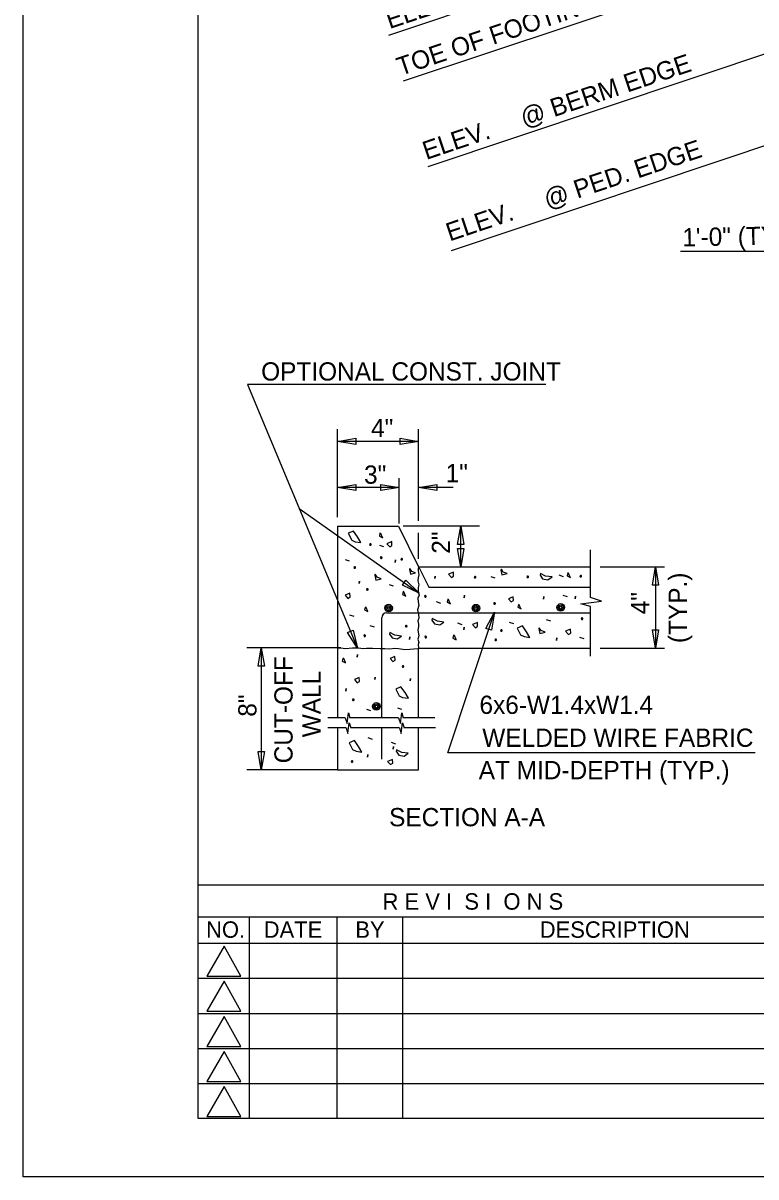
# Model space of a CAD drawing. Extents: x 0 to 272, y 0 to 188.
# Drawn here: x 0 to 50.2, y 0 to 79 of the extents above; entities that cross this region are included whole.
import ezdxf

# ---------------------------------------------------------------- set-up
doc = ezdxf.new("R2010")
doc.units = 0
for name, color, linetype in [('BORDER_ANNO_Cutsheet', 7, 'Continuous'), ('BRDG_ANNO_Anno-Sheet', 7, 'Continuous'), ('BRDG_ANNO_General-Notes', 7, 'Continuous'), ('BRDG_BASE_Active-Point', 7, 'Continuous'), ('BRDG_BASE_Hidden-Line', 7, 'Continuous'), ('BRDG_BASE_Obj-Line', 7, 'Continuous'), ('BRDG_BASE_Pattern', 7, 'Continuous'), ('BRDG_BASE_Rebar', 7, 'Continuous')]:
    doc.layers.add(name, color=color, linetype=linetype)

msp = doc.modelspace()

# ---------------------------------------------------------------- linework, layer by layer
at = {"layer": 'BORDER_ANNO_Cutsheet'}
msp.add_lwpolyline([(0, 176), (272, 176), (272, 0), (0, 0)], close=True, dxfattribs=at)
at = {"layer": 'BRDG_ANNO_Anno-Sheet'}
for p, q in [((12, 20), (154, 20)), ((12, 17.8), (56, 17.8)), ((15.5, 4), (15.5, 17.8)), ((21.5, 4), (21.5, 17.8)), ((26, 4), (26, 17.755)), ((11.98, 16), (56, 16)), ((11.98, 13.6), (56, 13.6)), ((11.98, 11.2), (56, 11.2)), ((11.98, 8.8), (56, 8.8)), ((11.98, 6.4), (56, 6.4))]:
    msp.add_line(p, q, dxfattribs=at)
msp.add_lwpolyline([(12, 172), (268, 172), (268, 4), (12, 4)], close=True, dxfattribs=at)
for points in [[(13.78, 15.795), (12.595, 13.74), (14.915, 13.74), (13.78, 15.795)], [(13.78, 13.395), (12.595, 11.34), (14.915, 11.34), (13.78, 13.395)], [(13.78, 10.995), (12.595, 8.94), (14.915, 8.94), (13.78, 10.995)], [(13.78, 8.595), (12.595, 6.54), (14.915, 6.54), (13.78, 8.595)], [(13.78, 6.195), (12.595, 4.14), (14.915, 4.14), (13.78, 6.195)]]:
    msp.add_lwpolyline(points, dxfattribs=at)
at = {"layer": 'BRDG_ANNO_General-Notes'}
for p, q in [((25.039, 78.187), (58.643, 89.43)), ((26.054, 75.048), (57.783, 85.664)), ((27.736, 69.191), (51.823, 77.251)), ((29.335, 63.443), (52.01, 71.029)), ((45.029, 63.39), (54.706, 63.39)), ((15.359, 54.256), (22.894, 36.209)), ((35.8, 54.256), (15.359, 54.256)), ((21.53, 45.18), (21.53, 51.205)), ((21.53, 50.37), (22.78, 50.578)), ((22.78, 50.578), (22.78, 50.162)), ((25.827, 50.162), (25.827, 50.578)), ((25.827, 50.578), (27.077, 50.37)), ((27.089, 44.917), (27.089, 51.205)), ((27.077, 50.37), (21.53, 50.37)), ((22.78, 50.162), (21.53, 50.37)), ((27.077, 50.37), (25.827, 50.162)), ((21.53, 47.213), (22.78, 47.422)), ((22.78, 47.422), (22.78, 47.005)), ((24.502, 47.005), (24.502, 47.422)), ((24.502, 47.422), (25.752, 47.213)), ((25.752, 44.74), (25.752, 47.838)), ((27.089, 47.213), (28.339, 47.422)), ((28.339, 47.422), (28.339, 47.005)), ((25.752, 47.213), (21.53, 47.213)), ((22.78, 47.005), (21.53, 47.213)), ((25.752, 47.213), (24.502, 47.005)), ((29.449, 47.213), (27.089, 47.213)), ((28.339, 47.005), (27.089, 47.213)), ((18.903, 45.769), (27.119, 39.965)), ((31.246, 44.555), (26.022, 44.555)), ((29.761, 43.305), (29.969, 44.555)), ((29.969, 41.784), (29.969, 44.555)), ((29.969, 44.555), (30.178, 43.305)), ((27.089, 42.32), (27.089, 44.102)), ((30.178, 43.305), (29.761, 43.305)), ((29.761, 43.034), (30.178, 43.034)), ((29.969, 41.784), (29.761, 43.034)), ((30.178, 43.034), (29.969, 41.784)), ((39.527, 41.776), (43.937, 41.776)), ((43.104, 40.526), (43.312, 41.776)), ((43.312, 41.776), (43.312, 36.217)), ((43.312, 41.776), (43.521, 40.526)), ((25.978, 40.516), (26.219, 40.856)), ((27.119, 39.965), (25.978, 40.516)), ((26.219, 40.856), (27.119, 39.965)), ((43.521, 40.526), (43.104, 40.526)), ((29.084, 29.032), (32.284, 38.684)), ((31.693, 37.563), (32.284, 38.684)), ((32.284, 38.684), (32.089, 37.432)), ((22.22, 37.282), (22.604, 37.443)), ((22.894, 36.209), (22.22, 37.282)), ((22.604, 37.443), (22.894, 36.209)), ((32.089, 37.432), (31.693, 37.563)), ((43.104, 37.467), (43.521, 37.467)), ((43.312, 36.217), (43.104, 37.467)), ((43.521, 37.467), (43.312, 36.217)), ((21.767, 36.221), (15.334, 36.221)), ((16.106, 34.971), (16.314, 36.221)), ((16.314, 36.221), (16.314, 27.878)), ((16.314, 36.221), (16.523, 34.971)), ((39.527, 36.217), (43.937, 36.217)), ((16.523, 34.971), (16.106, 34.971)), ((16.106, 29.128), (16.523, 29.128)), ((16.314, 27.878), (16.106, 29.128)), ((16.523, 29.128), (16.314, 27.878)), ((50.13, 29.032), (29.084, 29.032)), ((21.53, 27.878), (15.334, 27.878))]:
    msp.add_line(p, q, dxfattribs=at)
at = {"layer": 'BRDG_BASE_Active-Point'}
msp.add_line((0, 0), (0, 0), dxfattribs=at)
at = {"layer": 'BRDG_BASE_Hidden-Line'}
for p, q in [((27.123, 41.708), (27.782, 40.391)), ((27.782, 40.386), (38.869, 40.386))]:
    msp.add_line(p, q, dxfattribs=at)
at = {"layer": 'BRDG_BASE_Obj-Line'}
for p, q in [((21.53, 44.555), (25.699, 44.555)), ((21.53, 44.555), (21.53, 31.444)), ((25.699, 44.555), (27.089, 41.776)), ((38.869, 39.673), (38.869, 42.936)), ((27.089, 41.776), (27.093, 41.776)), ((27.089, 41.776), (38.869, 41.776)), ((39.619, 39.43), (38.869, 39.673)), ((38.197, 39.241), (39.619, 39.43)), ((38.869, 39.05), (38.197, 39.241)), ((38.869, 35.657), (38.869, 39.05)), ((27.089, 31.444), (27.089, 36.217)), ((27.089, 36.217), (38.869, 36.217)), ((22.194, 31.048), (22.29, 31.778)), ((22.29, 31.778), (22.388, 31.435)), ((25.844, 31.048), (25.941, 31.778)), ((25.941, 31.778), (26.038, 31.435)), ((22.069, 31.435), (20.875, 31.435)), ((22.069, 31.435), (22.194, 31.048)), ((22.242, 30.369), (22.338, 31.099)), ((22.338, 31.099), (22.437, 30.755)), ((25.72, 31.435), (22.388, 31.435)), ((25.72, 31.435), (25.844, 31.048)), ((25.893, 30.369), (25.99, 31.099)), ((25.99, 31.099), (26.087, 30.755)), ((28.198, 31.435), (26.038, 31.435)), ((22.117, 30.755), (20.874, 30.756)), ((21.53, 30.741), (21.53, 27.878)), ((22.117, 30.755), (22.242, 30.369)), ((25.769, 30.755), (22.437, 30.755)), ((25.769, 30.755), (25.893, 30.369)), ((28.246, 30.755), (26.087, 30.755)), ((27.089, 27.878), (27.089, 30.741)), ((21.53, 27.878), (27.089, 27.878))]:
    msp.add_line(p, q, dxfattribs=at)
for points in [[(27.094, 41.756), (27.063, 41.696), (27.054, 41.501), (27.104, 41.237), (27.063, 41.024), (27.033, 40.81), (27.104, 40.546), (27.054, 40.353), (27.054, 40.099), (27.124, 39.835), (27.023, 39.632), (27.054, 39.378), (27.094, 39.123), (27.013, 38.829), (27.074, 38.503), (27.104, 38.259), (27.023, 38.077), (27.084, 37.853), (27.084, 37.7), (27.044, 37.436), (27.104, 37.061), (27.023, 36.827), (27.094, 36.602), (27.063, 36.46), (27.074, 36.216)], [(21.538, 36.217), (21.767, 36.221), (22.072, 36.174), (22.553, 36.221), (22.976, 36.221), (23.293, 36.185), (23.516, 36.209), (23.927, 36.209), (24.455, 36.174), (24.783, 36.174), (25.112, 36.162), (25.453, 36.197), (25.711, 36.174), (26.145, 36.115), (26.497, 36.138), (26.755, 36.162), (27.084, 36.185)]]:
    msp.add_lwpolyline(points, dxfattribs=at)
at = {"layer": 'BRDG_BASE_Pattern'}
for p, q in [((24.399, 43.268), (24.687, 43.172)), ((22.053, 42.281), (22.342, 42.184)), ((32.028, 41.12), (32.316, 41.024)), ((36.694, 41.218), (36.982, 41.122)), ((25.066, 40.577), (25.354, 40.48)), ((36.966, 39.837), (37.254, 39.74)), ((28.3, 39.392), (28.588, 39.295)), ((22.353, 38.494), (22.641, 38.398)), ((29.756, 37.935), (30.044, 37.839)), ((33.287, 37.985), (33.576, 37.888)), ((35.824, 38.169), (36.113, 38.072)), ((23.757, 37.763), (24.045, 37.665)), ((38.107, 36.959), (38.395, 36.862)), ((23.51, 32.034), (23.799, 31.938)), ((25.633, 32.133), (25.922, 32.037)), ((23.609, 30.084), (23.898, 29.987)), ((25.213, 29.762), (25.502, 29.666))]:
    msp.add_line(p, q, dxfattribs=at)
for points in [[(22.274, 44.071), (22.504, 43.607), (22.737, 43.492), (23.141, 43.434), (22.91, 43.82), (22.621, 44.225)], [(24.4, 43.885), (24.633, 43.769), (24.614, 43.789), (24.497, 44.058), (24.44, 44.078)], [(24.913, 43.363), (25.109, 43.147), (25.263, 43.243), (25.244, 43.502)], [(23.72, 43.335), (23.749, 43.257), (23.807, 43.257), (23.84, 43.291), (23.84, 43.322), (23.812, 43.35), (23.793, 43.359), (23.762, 43.359)], [(24.462, 42.429), (24.491, 42.35), (24.549, 42.35), (24.583, 42.384), (24.583, 42.415), (24.554, 42.443), (24.535, 42.452), (24.505, 42.452)], [(25.491, 42.083), (25.51, 42.255)], [(25.865, 42.326), (25.894, 42.248), (25.952, 42.248), (25.986, 42.282), (25.986, 42.312), (25.957, 42.341), (25.938, 42.349), (25.908, 42.349)], [(22.646, 41.762), (22.675, 41.684), (22.732, 41.684), (22.767, 41.718), (22.767, 41.748), (22.738, 41.777), (22.719, 41.786), (22.689, 41.786)], [(24.084, 41.211), (24.152, 40.872), (24.515, 40.964), (24.248, 41.066), (24.114, 41.268)], [(26.455, 41.605), (26.523, 41.268), (26.884, 41.359), (26.619, 41.461), (26.484, 41.663)], [(28.207, 40.972), (28.225, 41.145)], [(29.136, 41.265), (29.332, 41.048), (29.485, 41.145), (29.467, 41.404)], [(30.892, 41.095), (30.921, 41.017), (30.979, 41.017), (31.013, 41.051), (31.013, 41.081), (30.984, 41.11), (30.965, 41.119), (30.935, 41.119)], [(32.725, 41.557), (32.793, 41.218), (33.155, 41.31), (32.889, 41.411), (32.755, 41.614)], [(34.496, 41.12), (34.525, 41.042), (34.583, 41.042), (34.617, 41.076), (34.617, 41.106), (34.588, 41.135), (34.57, 41.143), (34.539, 41.143)], [(35.407, 41.216), (35.582, 40.958), (35.937, 40.89), (36.227, 41.083), (35.779, 41.145), (35.431, 41.328)], [(37.264, 41.17), (37.496, 41.053), (37.477, 41.073), (37.361, 41.343), (37.303, 41.362)], [(38.125, 41.17), (38.154, 41.091), (38.212, 41.091), (38.246, 41.126), (38.246, 41.156), (38.218, 41.185), (38.198, 41.193), (38.168, 41.193)], [(23.022, 40.626), (23.041, 40.799)], [(22.049, 39.833), (22.246, 39.617), (22.399, 39.713), (22.381, 39.972)], [(23.51, 40.256), (23.539, 40.178), (23.597, 40.178), (23.631, 40.212), (23.631, 40.242), (23.602, 40.271), (23.583, 40.279), (23.552, 40.279)], [(25.981, 39.886), (26.213, 39.77), (26.194, 39.79), (26.078, 40.059), (26.019, 40.079)], [(27.485, 39.787), (27.513, 39.708), (27.572, 39.708), (27.605, 39.743), (27.605, 39.773), (27.577, 39.802), (27.558, 39.81), (27.527, 39.81)], [(29.042, 39.368), (29.275, 39.251), (29.256, 39.271), (29.139, 39.54), (29.081, 39.56)], [(30.206, 39.663), (30.225, 39.837)], [(33.233, 39.585), (33.43, 39.369), (33.583, 39.465), (33.565, 39.724)], [(35.637, 39.565), (35.657, 39.738)], [(37.811, 39.589), (37.83, 39.762)], [(23.389, 38.824), (23.621, 38.708), (23.602, 38.727), (23.486, 38.996), (23.427, 39.017)], [(32.225, 39.294), (32.253, 39.215), (32.311, 39.215), (32.346, 39.25), (32.346, 39.28), (32.317, 39.308), (32.297, 39.317), (32.267, 39.317)], [(33.882, 39.007), (34.114, 38.891), (34.095, 38.91), (33.979, 39.18), (33.921, 39.2)], [(28.001, 38.131), (28.175, 37.872), (28.531, 37.804), (28.82, 37.997), (28.371, 38.059), (28.025, 38.242)], [(30.779, 37.823), (30.975, 37.606), (31.128, 37.703), (31.11, 37.962)], [(38.224, 38.256), (38.252, 38.178), (38.311, 38.178), (38.345, 38.212), (38.345, 38.242), (38.316, 38.271), (38.297, 38.28), (38.266, 38.28)], [(25.093, 37.165), (25.267, 36.906), (25.623, 36.838), (25.912, 37.031), (25.464, 37.093), (25.117, 37.276)], [(26.177, 37.738), (26.205, 37.66), (26.264, 37.66), (26.297, 37.693), (26.297, 37.724), (26.269, 37.752), (26.25, 37.761), (26.219, 37.761)], [(30.182, 37.466), (30.201, 37.639)], [(32.693, 37.442), (32.723, 37.363), (32.78, 37.363), (32.815, 37.398), (32.815, 37.428), (32.786, 37.457), (32.767, 37.465), (32.736, 37.465)], [(33.844, 37.574), (34.074, 37.11), (34.307, 36.995), (34.711, 36.937), (34.479, 37.323), (34.191, 37.728)], [(35.323, 37.551), (35.39, 37.214), (35.753, 37.304), (35.487, 37.406), (35.352, 37.608)], [(37.158, 37.363), (37.355, 37.148), (37.509, 37.244), (37.49, 37.502)], [(23.337, 37.087), (23.366, 37.009), (23.424, 37.009), (23.458, 37.043), (23.458, 37.073), (23.43, 37.102), (23.41, 37.111), (23.38, 37.111)], [(26.463, 36.808), (26.482, 36.981)], [(27.51, 36.997), (27.539, 36.919), (27.597, 36.919), (27.631, 36.953), (27.631, 36.983), (27.602, 37.012), (27.583, 37.021), (27.553, 37.021)], [(29.437, 36.898), (29.669, 36.781), (29.65, 36.802), (29.534, 37.071), (29.476, 37.091)], [(32.302, 36.801), (32.33, 36.723), (32.389, 36.723), (32.422, 36.757), (32.422, 36.787), (32.394, 36.815), (32.375, 36.824), (32.344, 36.824)], [(36.53, 36.736), (36.549, 36.909)], [(22.875, 35.59), (22.893, 35.763)], [(25.132, 35.504), (25.328, 35.287), (25.482, 35.384), (25.464, 35.643)], [(21.858, 35.318), (22.091, 35.202), (22.072, 35.221), (21.955, 35.491), (21.897, 35.511)], [(25.954, 34.973), (25.983, 34.895), (26.041, 34.895), (26.075, 34.929), (26.075, 34.959), (26.047, 34.988), (26.027, 34.997), (25.997, 34.997)], [(22.691, 34.056), (22.887, 33.839), (23.041, 33.935), (23.023, 34.195)], [(24.084, 34.059), (24.103, 34.233)], [(26.503, 33.96), (26.523, 34.133)], [(22.109, 33.268), (22.128, 33.441)], [(25.524, 33.411), (25.754, 32.947), (25.986, 32.833), (26.391, 32.775), (26.159, 33.161), (25.87, 33.566)], [(22.548, 32.701), (22.576, 32.623), (22.635, 32.623), (22.668, 32.657), (22.668, 32.687), (22.64, 32.716), (22.621, 32.725), (22.59, 32.725)], [(22.34, 29.733), (22.569, 29.269), (22.802, 29.155), (23.206, 29.096), (22.975, 29.482), (22.686, 29.887)], [(25.343, 29.294), (25.362, 29.466)], [(25.557, 29.143), (25.731, 28.884), (26.087, 28.816), (26.375, 29.009), (25.927, 29.072), (25.581, 29.254)], [(22.473, 28.479), (22.502, 28.4), (22.56, 28.4), (22.594, 28.434), (22.594, 28.465), (22.565, 28.493), (22.546, 28.502), (22.516, 28.502)], [(23.59, 28.75), (23.609, 28.924)], [(24.963, 28.45), (25.159, 28.234), (25.312, 28.33), (25.294, 28.589)]]:
    msp.add_lwpolyline(points, close=True, dxfattribs=at)
at = {"layer": 'BRDG_BASE_Rebar'}
for p, q in [((24.563, 31.416), (24.563, 38.291)), ((24.911, 38.638), (38.869, 38.638)), ((24.563, 28.602), (24.563, 30.755))]:
    msp.add_line(p, q, dxfattribs=at)
for centre, radius in [((25.033, 38.956), 0.26), ((25.033, 38.956), 0.173), ((25.033, 38.956), 0.0866), ((31.016, 38.947), 0.26), ((31.016, 38.947), 0.173), ((31.016, 38.947), 0.0866), ((36.817, 38.996), 0.26), ((36.817, 38.996), 0.173), ((36.817, 38.996), 0.0866), ((24.198, 32.217), 0.26), ((24.198, 32.217), 0.173), ((24.198, 32.217), 0.0866)]:
    msp.add_circle(centre, radius, dxfattribs=at)
msp.add_arc((24.911, 38.29), 0.347, 90, 180, dxfattribs=at)

# ---------------------------------------------------------------- texts
at = {"layer": 'BRDG_ANNO_Anno-Sheet'}
for s, p in [('R E V I  S I  O N S', (24.619, 18.3)), ('NO.', (12.533, 16.375)), ('DATE', (16.48, 16.375)), ('BY', (22.753, 16.375)), ('DESCRIPTION', (35.382, 16.375))]:
    msp.add_text(s, height=1.125, dxfattribs=at).set_placement(p)
at = {"layer": 'BRDG_ANNO_General-Notes'}
for s, rotation, p in [('ELEV.        @ BERM EDGE', 18.50001, (25.095, 78.599)), ('TOE OF FOOTING', 18.5, (25.842, 75.394)), ('ELEV.     @ BERM EDGE', 18.50001, (27.61, 69.639)), ('ELEV.     @ PED. EDGE', 18.50001, (29.213, 64.056)), ('1\'-0" (TYP.)', 1.1, (45.159, 63.714)), ('2"', 90, (29.242, 42.674)), ('(TYP.)', 90, (45.456, 36.555)), ('4"', 90, (42.888, 38.527)), ('CUT-OFF  ', 90, (18.458, 28.321)), ('WALL', 90, (20.383, 30.105)), ('8"', 90, (15.984, 31.514))]:
    msp.add_text(s, height=1.25, rotation=rotation, dxfattribs=at).set_placement(p)
for s, p in [('OPTIONAL CONST. JOINT', (16.305, 54.533)), ('4"', (23.832, 50.657)), ('3"', (23.352, 47.467)), ('1"', (28.939, 47.571)), ('6x6-W1.4xW1.4', (31.255, 31.705)), ('WELDED WIRE FABRIC', (31.448, 29.451)), ('AT MID-DEPTH (TYP.)', (31.205, 27.232)), ('SECTION A-A', (25.067, 24.012))]:
    msp.add_text(s, height=1.25, dxfattribs=at).set_placement(p)

doc.saveas('drawing.dxf')
